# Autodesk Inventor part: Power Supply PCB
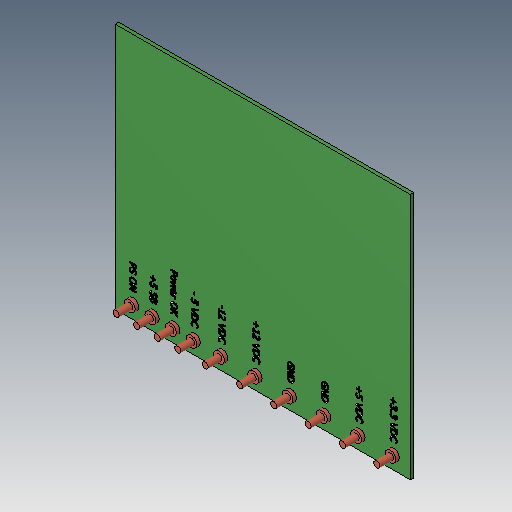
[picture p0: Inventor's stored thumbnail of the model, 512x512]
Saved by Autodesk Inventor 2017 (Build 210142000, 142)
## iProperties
Created: 2006-09
Part Number: Power Supply PCB
Material: Generic
Document SubType Name: Modeling
Designer: DanielSeverino
Density: 1 g/cm^3
Appearance: Default
Author: DanielSeverino
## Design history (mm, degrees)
feature "Solid1"
body "Solid2"
